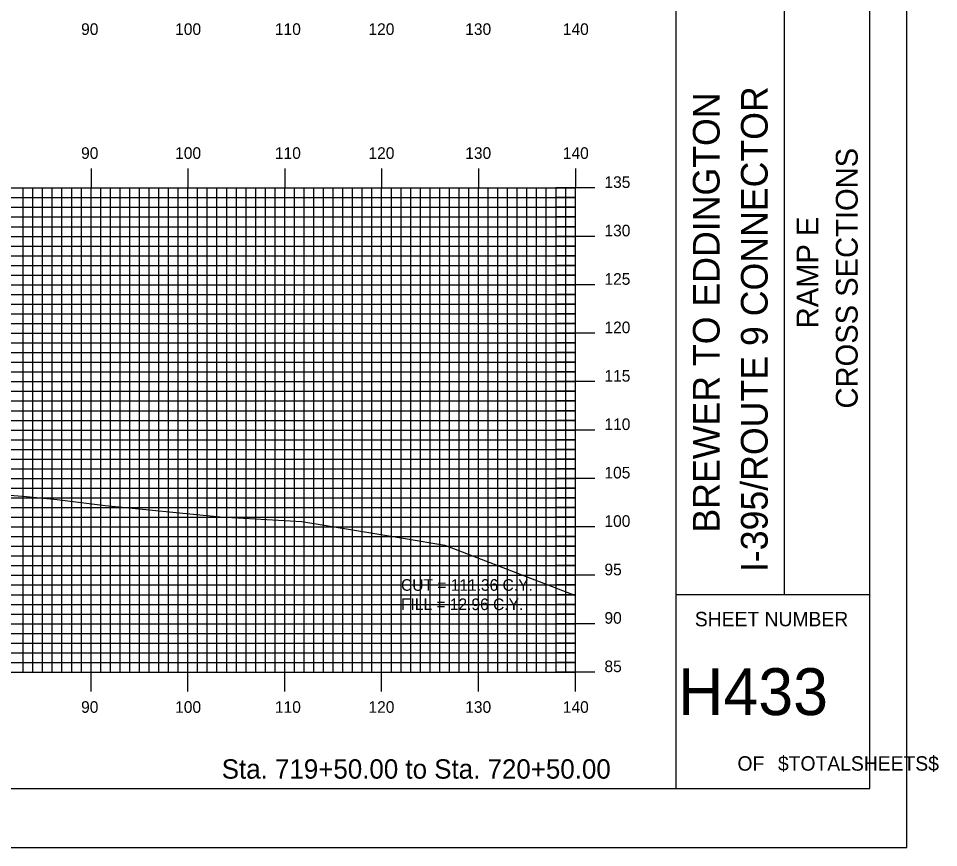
# Model space of a CAD drawing. Extents: x 858052 to 858395, y 364366 to 364586.
# Drawn here: x 858299.9 to 858394.9, y 364365.7 to 364451.3 of the extents above; entities that cross this region are included whole.
import ezdxf

# ---------------------------------------------------------------- set-up
doc = ezdxf.new("R2010")
doc.units = 0
for name, color, linetype in [('BORDER', 7, 'Continuous'), ('D_Text_Standard', 7, 'Continuous'), ('H_V ANNOTATION', 7, 'Continuous'), ('M_Utilities_Pole', 7, 'Continuous'), ('MAJOR', 7, 'Continuous'), ('MINOR', 7, 'Continuous'), ('PLOT BOUNDARY', 7, 'Continuous'), ('S_Roadway_Centerline', 7, 'Continuous')]:
    doc.layers.add(name, color=color, linetype=linetype)

msp = doc.modelspace()

# ---------------------------------------------------------------- linework, layer by layer
at = {"layer": 'BORDER'}
for p, q in [((858367.762, 364371.787), (858367.762, 364581.787)), ((858378.944, 364391.793), (858378.944, 364461.793)), ((858367.762, 364391.793), (858387.762, 364391.793))]:
    msp.add_line(p, q, dxfattribs=at)
msp.add_lwpolyline([(858067.762, 364371.787), (858387.762, 364371.787), (858387.762, 364581.787), (858067.762, 364581.787)], close=True, dxfattribs=at)
at = {"layer": 'M_Utilities_Pole'}
msp.add_line((858342.568, 364399.111), (858342.568, 364399.094), dxfattribs=at)
msp.add_circle((858342.568, 364399.103), 0.00417, dxfattribs=at)
at = {"layer": 'MAJOR'}
for p, q in [((858307.362, 364435.791), (858307.362, 364433.787)), ((858317.362, 364435.791), (858317.362, 364433.787)), ((858327.362, 364435.791), (858327.362, 364433.787)), ((858337.362, 364435.791), (858337.362, 364433.787)), ((858347.362, 364435.791), (858347.362, 364433.787)), ((858357.362, 364435.791), (858357.362, 364433.787)), ((858077.362, 364433.787), (858357.362, 364433.787)), ((858077.362, 364433.787), (858357.362, 364433.787)), ((858307.362, 364383.787), (858307.362, 364433.787)), ((858317.362, 364383.787), (858317.362, 364433.787)), ((858327.362, 364383.787), (858327.362, 364433.787)), ((858337.362, 364383.787), (858337.362, 364433.787)), ((858347.362, 364383.787), (858347.362, 364433.787)), ((858359.366, 364433.787), (858355.358, 364433.787)), ((858357.362, 364383.787), (858357.362, 364433.787)), ((858357.362, 364383.787), (858357.362, 364433.787)), ((858077.362, 364428.787), (858357.362, 364428.787)), ((858359.366, 364428.787), (858355.358, 364428.787)), ((858077.362, 364423.787), (858357.362, 364423.787)), ((858359.366, 364423.787), (858355.358, 364423.787)), ((858077.362, 364418.787), (858357.362, 364418.787)), ((858359.366, 364418.787), (858355.358, 364418.787)), ((858077.362, 364413.787), (858357.362, 364413.787)), ((858359.366, 364413.787), (858355.358, 364413.787)), ((858077.362, 364408.787), (858357.362, 364408.787)), ((858359.366, 364408.787), (858355.358, 364408.787)), ((858077.362, 364403.787), (858357.362, 364403.787)), ((858359.366, 364403.787), (858355.358, 364403.787)), ((858077.362, 364398.787), (858357.362, 364398.787)), ((858359.366, 364398.787), (858355.358, 364398.787)), ((858077.362, 364393.787), (858357.362, 364393.787)), ((858359.366, 364393.787), (858355.358, 364393.787)), ((858077.362, 364388.787), (858357.362, 364388.787)), ((858359.366, 364388.787), (858355.358, 364388.787)), ((858077.362, 364383.787), (858357.362, 364383.787)), ((858077.362, 364383.787), (858357.362, 364383.787)), ((858307.362, 364381.783), (858307.362, 364383.787)), ((858317.362, 364381.783), (858317.362, 364383.787)), ((858327.362, 364381.783), (858327.362, 364383.787)), ((858337.362, 364381.783), (858337.362, 364383.787)), ((858347.362, 364381.783), (858347.362, 364383.787)), ((858359.366, 364383.787), (858355.358, 364383.787)), ((858357.362, 364381.783), (858357.362, 364383.787))]:
    msp.add_line(p, q, dxfattribs=at)
at = {"layer": 'MINOR'}
for p, q in [((858300.362, 364383.787), (858300.362, 364433.787)), ((858301.362, 364383.787), (858301.362, 364433.787)), ((858302.362, 364383.787), (858302.362, 364433.787)), ((858303.362, 364383.787), (858303.362, 364433.787)), ((858304.362, 364383.787), (858304.362, 364433.787)), ((858305.362, 364383.787), (858305.362, 364433.787)), ((858306.362, 364383.787), (858306.362, 364433.787)), ((858308.362, 364383.787), (858308.362, 364433.787)), ((858309.362, 364383.787), (858309.362, 364433.787)), ((858310.362, 364383.787), (858310.362, 364433.787)), ((858311.362, 364383.787), (858311.362, 364433.787)), ((858312.362, 364383.787), (858312.362, 364433.787)), ((858313.362, 364383.787), (858313.362, 364433.787)), ((858314.362, 364383.787), (858314.362, 364433.787)), ((858315.362, 364383.787), (858315.362, 364433.787)), ((858316.362, 364383.787), (858316.362, 364433.787)), ((858318.362, 364383.787), (858318.362, 364433.787)), ((858319.362, 364383.787), (858319.362, 364433.787)), ((858320.362, 364383.787), (858320.362, 364433.787)), ((858321.362, 364383.787), (858321.362, 364433.787)), ((858322.362, 364383.787), (858322.362, 364433.787)), ((858323.362, 364383.787), (858323.362, 364433.787)), ((858324.362, 364383.787), (858324.362, 364433.787)), ((858325.362, 364383.787), (858325.362, 364433.787)), ((858326.362, 364383.787), (858326.362, 364433.787)), ((858328.362, 364383.787), (858328.362, 364433.787)), ((858329.362, 364383.787), (858329.362, 364433.787)), ((858330.362, 364383.787), (858330.362, 364433.787)), ((858331.362, 364383.787), (858331.362, 364433.787)), ((858332.362, 364383.787), (858332.362, 364433.787)), ((858333.362, 364383.787), (858333.362, 364433.787)), ((858334.362, 364383.787), (858334.362, 364433.787)), ((858335.362, 364383.787), (858335.362, 364433.787)), ((858336.362, 364383.787), (858336.362, 364433.787)), ((858338.362, 364383.787), (858338.362, 364433.787)), ((858339.362, 364383.787), (858339.362, 364433.787)), ((858340.362, 364383.787), (858340.362, 364433.787)), ((858341.362, 364383.787), (858341.362, 364433.787)), ((858342.362, 364383.787), (858342.362, 364433.787)), ((858343.362, 364383.787), (858343.362, 364433.787)), ((858344.362, 364383.787), (858344.362, 364433.787)), ((858345.362, 364383.787), (858345.362, 364433.787)), ((858346.362, 364383.787), (858346.362, 364433.787)), ((858348.362, 364383.787), (858348.362, 364433.787)), ((858349.362, 364383.787), (858349.362, 364433.787)), ((858350.362, 364383.787), (858350.362, 364433.787)), ((858351.362, 364383.787), (858351.362, 364433.787)), ((858352.362, 364383.787), (858352.362, 364433.787)), ((858353.362, 364383.787), (858353.362, 364433.787)), ((858354.362, 364383.787), (858354.362, 364433.787)), ((858355.362, 364383.787), (858355.362, 364433.787)), ((858356.362, 364383.787), (858356.362, 364433.787)), ((858077.362, 364432.787), (858357.362, 364432.787)), ((858357.362, 364432.787), (858355.358, 364432.787)), ((858077.362, 364431.787), (858357.362, 364431.787)), ((858357.362, 364431.787), (858355.358, 364431.787)), ((858077.362, 364430.787), (858357.362, 364430.787)), ((858357.362, 364430.787), (858355.358, 364430.787)), ((858077.362, 364429.787), (858357.362, 364429.787)), ((858357.362, 364429.787), (858355.358, 364429.787)), ((858077.362, 364427.787), (858357.362, 364427.787)), ((858357.362, 364427.787), (858355.358, 364427.787)), ((858077.362, 364426.787), (858357.362, 364426.787)), ((858357.362, 364426.787), (858355.358, 364426.787)), ((858077.362, 364425.787), (858357.362, 364425.787)), ((858357.362, 364425.787), (858355.358, 364425.787)), ((858077.362, 364424.787), (858357.362, 364424.787)), ((858357.362, 364424.787), (858355.358, 364424.787)), ((858077.362, 364422.787), (858357.362, 364422.787)), ((858357.362, 364422.787), (858355.358, 364422.787)), ((858077.362, 364421.787), (858357.362, 364421.787)), ((858357.362, 364421.787), (858355.358, 364421.787)), ((858077.362, 364420.787), (858357.362, 364420.787)), ((858357.362, 364420.787), (858355.358, 364420.787)), ((858077.362, 364419.787), (858357.362, 364419.787)), ((858357.362, 364419.787), (858355.358, 364419.787)), ((858077.362, 364417.787), (858357.362, 364417.787)), ((858357.362, 364417.787), (858355.358, 364417.787)), ((858077.362, 364416.787), (858357.362, 364416.787)), ((858357.362, 364416.787), (858355.358, 364416.787)), ((858077.362, 364415.787), (858357.362, 364415.787)), ((858357.362, 364415.787), (858355.358, 364415.787)), ((858077.362, 364414.787), (858357.362, 364414.787)), ((858357.362, 364414.787), (858355.358, 364414.787)), ((858077.362, 364412.787), (858357.362, 364412.787)), ((858357.362, 364412.787), (858355.358, 364412.787)), ((858077.362, 364411.787), (858357.362, 364411.787)), ((858357.362, 364411.787), (858355.358, 364411.787)), ((858077.362, 364410.787), (858357.362, 364410.787)), ((858357.362, 364410.787), (858355.358, 364410.787)), ((858077.362, 364409.787), (858357.362, 364409.787)), ((858357.362, 364409.787), (858355.358, 364409.787)), ((858077.362, 364407.787), (858357.362, 364407.787)), ((858357.362, 364407.787), (858355.358, 364407.787)), ((858077.362, 364406.787), (858357.362, 364406.787)), ((858357.362, 364406.787), (858355.358, 364406.787)), ((858077.362, 364405.787), (858357.362, 364405.787)), ((858357.362, 364405.787), (858355.358, 364405.787)), ((858077.362, 364404.787), (858357.362, 364404.787)), ((858357.362, 364404.787), (858355.358, 364404.787)), ((858077.362, 364402.787), (858357.362, 364402.787)), ((858357.362, 364402.787), (858355.358, 364402.787)), ((858077.362, 364401.787), (858357.362, 364401.787)), ((858357.362, 364401.787), (858355.358, 364401.787)), ((858077.362, 364400.787), (858357.362, 364400.787)), ((858357.362, 364400.787), (858355.358, 364400.787)), ((858077.362, 364399.787), (858357.362, 364399.787)), ((858357.362, 364399.787), (858355.358, 364399.787)), ((858077.362, 364397.787), (858357.362, 364397.787)), ((858357.362, 364397.787), (858355.358, 364397.787)), ((858077.362, 364396.787), (858357.362, 364396.787)), ((858357.362, 364396.787), (858355.358, 364396.787)), ((858077.362, 364395.787), (858357.362, 364395.787)), ((858357.362, 364395.787), (858355.358, 364395.787)), ((858077.362, 364394.787), (858357.362, 364394.787)), ((858357.362, 364394.787), (858355.358, 364394.787)), ((858077.362, 364392.787), (858357.362, 364392.787)), ((858357.362, 364392.787), (858355.358, 364392.787)), ((858077.362, 364391.787), (858357.362, 364391.787)), ((858357.362, 364391.787), (858355.358, 364391.787)), ((858077.362, 364390.787), (858357.362, 364390.787)), ((858357.362, 364390.787), (858355.358, 364390.787)), ((858077.362, 364389.787), (858357.362, 364389.787)), ((858357.362, 364389.787), (858355.358, 364389.787)), ((858077.362, 364387.787), (858357.362, 364387.787)), ((858357.362, 364387.787), (858355.358, 364387.787)), ((858077.362, 364386.787), (858357.362, 364386.787)), ((858357.362, 364386.787), (858355.358, 364386.787)), ((858077.362, 364385.787), (858357.362, 364385.787)), ((858357.362, 364385.787), (858355.358, 364385.787)), ((858077.362, 364384.787), (858357.362, 364384.787)), ((858357.362, 364384.787), (858355.358, 364384.787))]:
    msp.add_line(p, q, dxfattribs=at)
at = {"layer": 'PLOT BOUNDARY'}
msp.add_lwpolyline([(858051.575, 364365.669), (858391.575, 364365.669), (858391.575, 364585.669), (858051.575, 364585.669)], close=True, dxfattribs=at)
at = {"layer": 'S_Roadway_Centerline'}
msp.add_lwpolyline([(858286.703, 364403.02), (858300.682, 364401.923), (858303.855, 364401.612), (858308.819, 364401), (858320.68, 364399.821), (858329.126, 364399.327), (858339.773, 364397.586), (858343.882, 364396.883), (858357.362, 364391.698)], dxfattribs=at)

# ---------------------------------------------------------------- texts
at = {"layer": 'BORDER'}
for s, height, p in [('I-395/ROUTE 9 CONNECTOR', 2.75575, (858377.211, 364394.117)), ('BREWER TO EDDINGTON', 2.75575, (858372.25, 364398.196)), ('CROSS SECTIONS', 2.25, (858386.503, 364411.009)), ('RAMP E', 2.25, (858382.453, 364419.291))]:
    msp.add_text(s, height=height, rotation=90, dxfattribs=at).set_placement(p)
for s, height, p in [('SHEET NUMBER', 1.49054, (858369.693, 364388.52)), ('H433', 4.8388, (858367.972, 364379.352)), ('OF', 1.4905, (858374.095, 364373.613)), ('$TOTALSHEETS$', 1.49054, (858378.275, 364373.613))]:
    msp.add_text(s, height=height, dxfattribs=at).set_placement(p)
at = {"layer": 'D_Text_Standard'}
for s, p in [('CUT = 111.36 C.Y.', (858339.362, 364392.187)), ('FILL = 12.96 C.Y.', (858339.362, 364390.195))]:
    msp.add_text(s, height=1.2, dxfattribs=at).set_placement(p)
at = {"layer": 'H_V ANNOTATION'}
for s, height, p in [('90', 1.2, (858306.334, 364449.587)), ('100', 1.2, (858316.045, 364449.587)), ('110', 1.2, (858326.345, 364449.587)), ('120', 1.2, (858336.002, 364449.587)), ('130', 1.2, (858345.992, 364449.587)), ('140', 1.2, (858356.066, 364449.587)), ('90', 1.2, (858306.334, 364436.787)), ('100', 1.2, (858316.045, 364436.787)), ('110', 1.2, (858326.345, 364436.787)), ('120', 1.2, (858336.002, 364436.787)), ('130', 1.2, (858345.992, 364436.787)), ('140', 1.2, (858356.066, 364436.787)), ('135', 1.2, (858360.362, 364433.787)), ('130', 1.2, (858360.362, 364428.787)), ('125', 1.2, (858360.362, 364423.787)), ('120', 1.2, (858360.362, 364418.787)), ('115', 1.2, (858360.362, 364413.787)), ('110', 1.2, (858360.362, 364408.787)), ('105', 1.2, (858360.362, 364403.787)), ('100', 1.2, (858360.362, 364398.787)), ('95', 1.2, (858360.362, 364393.787)), ('90', 1.2, (858360.362, 364388.787)), ('85', 1.2, (858360.362, 364383.787)), ('90', 1.2, (858306.334, 364379.587)), ('100', 1.2, (858316.045, 364379.587)), ('110', 1.2, (858326.345, 364379.587)), ('120', 1.2, (858336.002, 364379.587)), ('130', 1.2, (858345.992, 364379.587)), ('140', 1.2, (858356.066, 364379.587)), ('Sta. 719+50.00 to Sta. 720+50.00', 2.0004, (858320.853, 364372.787))]:
    msp.add_text(s, height=height, dxfattribs=at).set_placement(p)

doc.saveas('drawing.dxf')
